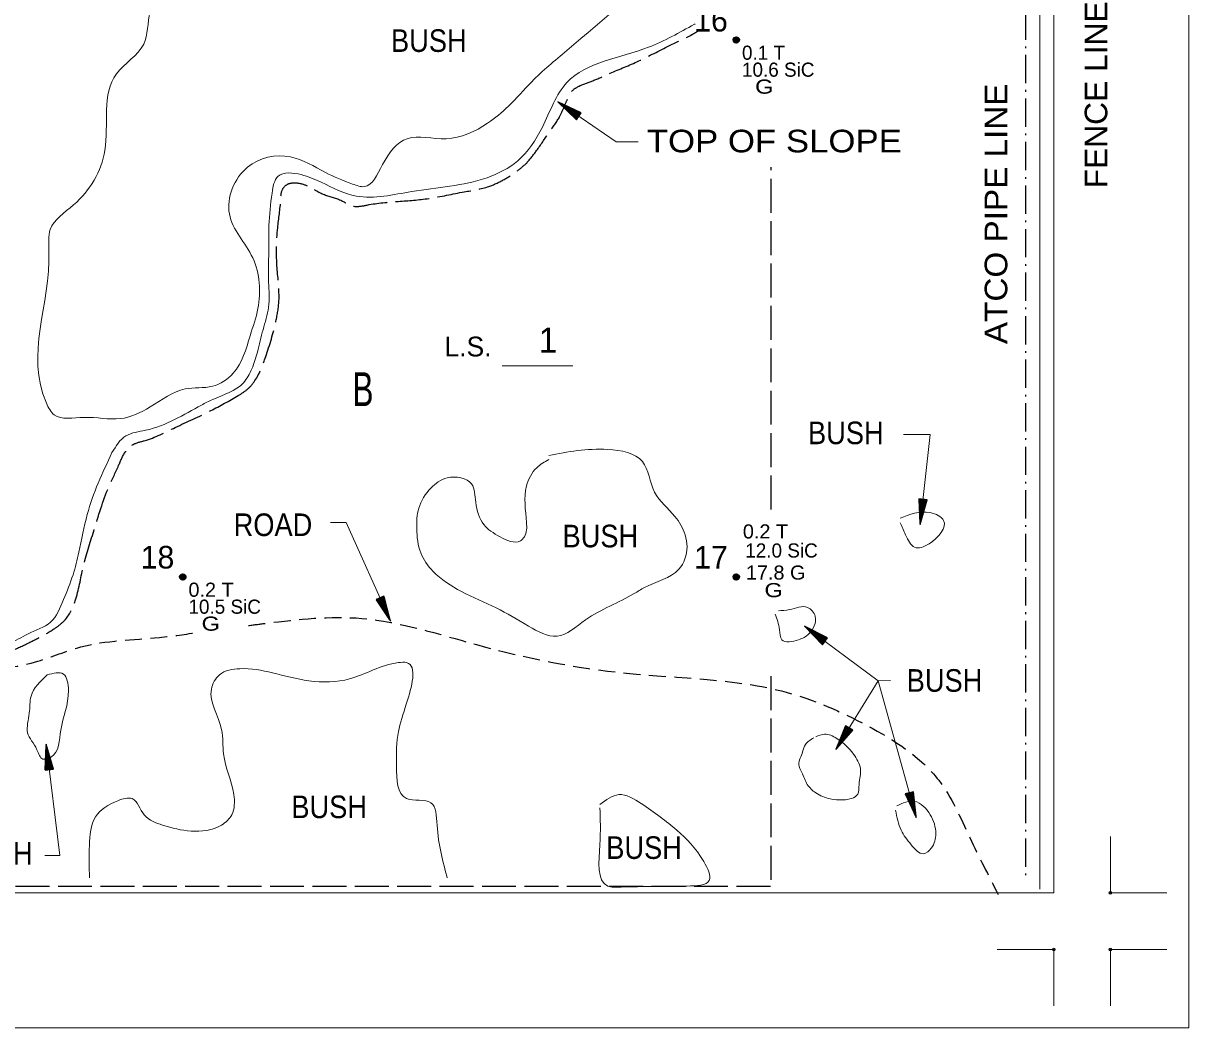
# Model space of a CAD drawing. Extents: x -496 to 480, y -450 to 700.
# Drawn here: x 37.7 to 450, y -450 to -94.7 of the extents above; entities that cross this region are included whole.
import ezdxf
from ezdxf.enums import TextEntityAlignment as Align

# ---------------------------------------------------------------- set-up
doc = ezdxf.new("R2010")
doc.units = 0
doc.header["$LTSCALE"] = 2
doc.header["$PDMODE"] = 32
doc.header["$PDSIZE"] = 1
for name, pattern in [('DOT_DASHED', [7.7, 5, -1.2, 0.3, -1.2]), ('LONG_DASHED', [7.5, 6, -1.5]), ('MEDIUM_DASHED', [4.5, 3, -1.5])]:
    doc.linetypes.add(name, pattern=pattern)
for name, color, linetype, lineweight in [('1', 7, 'Continuous', 13), ('2', 7, 'Continuous', 35), ('3', 7, 'Continuous', 13), ('4', 7, 'Continuous', 25)]:
    doc.layers.add(name, color=color, linetype=linetype, lineweight=lineweight)

msp = doc.modelspace()

# ---------------------------------------------------------------- linework, layer by layer
at = {"layer": '1'}
for p, q in [((207.114, -215.907), (232.114, -215.907)), ((422.281, -402.333), (422.281, -382.333)), ((-402.391, -402.333), (402.281, -402.333)), ((422.281, -402.333), (442.281, -402.333)), ((402.281, -422.333), (382.281, -422.333)), ((402.281, -422.333), (402.281, -442.333)), ((422.281, -422.333), (422.281, -442.333)), ((422.281, -422.333), (442.281, -422.333)), ((-450.017, -450.027), (449.983, -450.027))]:
    msp.add_line(p, q, dxfattribs=at)
for points in [[(449.983, -450.027), (449.983, 399.973), (449.983, 699.973), (-450.017, 699.973), (-450.017, 49.973), (-450.017, -450.027)], [(402.281, -402.333), (402.281, 402.339), (-402.391, 402.339)]]:
    msp.add_lwpolyline(points, dxfattribs=at)
for p in [(422.281, -402.333), (402.281, -422.333), (422.281, -422.333)]:
    msp.add_point(p, dxfattribs=at)
at = {"layer": '2', "linetype": 'LONG_DASHED', "lineweight": 25}
for p, q in [((302.281, -266.667), (302.281, -145.612)), ((302.281, -397.661), (302.281, -324.751)), ((-400, -400), (302.281, -400))]:
    msp.add_line(p, q, dxfattribs=at)
at = {"layer": '2'}
for centre in [(289.948, -100.57), (94.135, -290.569), (289.948, -290.569)]:
    msp.add_circle(centre, 1, dxfattribs=at)
at = {"layer": '2', "linetype": 'LONG_DASHED', "lineweight": 25}
for points in [[(215.795, -144.123), (219.291, -139.726), (223.65, -133.35), (227.23, -128.063), (229.099, -124.02), (230.5, -120.91), (231.745, -118.733), (234.392, -116.867), (239.53, -114.845), (245.29, -112.357), (255.409, -108.003), (266.307, -102.561), (274.247, -98.673), (276.582, -97.273)], [(113.75, -226.394), (117.11, -224.04), (119.657, -221.072), (123.477, -212.593), (127.085, -200.086), (128.146, -192.879), (127.509, -181.22), (127.721, -167.017), (128.782, -157.054), (129.419, -153.45), (131.329, -151.542), (133.451, -151.118), (137.696, -151.966), (143.85, -155.146), (150.005, -157.266), (154.674, -159.386), (159.343, -158.962), (170.379, -157.69), (181.202, -156.63), (193.724, -154.298), (202.425, -152.39), (207.519, -150.059), (212.188, -147.091), (215.795, -144.123)], [(17.819, -315.951), (23.775, -317.83), (30.672, -317.517), (37.256, -315.012), (43.526, -311.88), (48.855, -308.749), (52.304, -305.931), (56.066, -299.042), (58.887, -287.142), (62.649, -274.304), (67.979, -258.647), (71.427, -251.132), (73.935, -246.122), (76.13, -243.93), (80.519, -242.364), (91.491, -237.667), (104.031, -231.717), (113.75, -226.394)]]:
    msp.add_spline(points, degree=3, dxfattribs=at)
at = {"layer": '2'}
for points in [[(289.937, -99.683), (290.668, -100.087), (290.819, -100.936), (290.134, -101.464), (289.325, -101.233), (289.039, -100.475), (289.286, -99.913), (289.859, -99.745), (290.533, -100.239), (290.516, -100.981), (289.999, -101.239), (289.477, -101.07), (289.252, -100.424), (289.836, -99.958), (290.274, -100.492), (290.235, -100.975), (289.606, -100.84), (289.752, -100.205), (290.044, -100.756)], [(94.124, -289.682), (94.855, -290.086), (95.006, -290.935), (94.321, -291.463), (93.512, -291.232), (93.226, -290.474), (93.473, -289.912), (94.046, -289.744), (94.72, -290.238), (94.703, -290.98), (94.186, -291.238), (93.664, -291.069), (93.439, -290.423), (94.023, -289.957), (94.461, -290.491), (94.422, -290.974), (93.793, -290.839), (93.939, -290.204), (94.231, -290.755)], [(289.937, -289.682), (290.668, -290.086), (290.819, -290.935), (290.134, -291.463), (289.325, -291.232), (289.039, -290.474), (289.286, -289.912), (289.859, -289.744), (290.533, -290.238), (290.516, -290.98), (289.999, -291.238), (289.477, -291.069), (289.252, -290.423), (289.836, -289.957), (290.274, -290.491), (290.235, -290.974), (289.606, -290.839), (289.752, -290.204), (290.044, -290.755)]]:
    msp.add_spline(points, degree=3, dxfattribs=at)
at = {"layer": '3', "linetype": 'DOT_DASHED', "lineweight": 25}
msp.add_line((392.281, 402.339), (392.281, -396.11), dxfattribs=at)
at = {"layer": '3'}
msp.add_line((397.281, -401.02), (397.281, 402.339), dxfattribs=at)
for points in [[(269.001, 16.283), (271.297, 22.245), (282.315, 14.908), (294.71, 5.278), (300.22, -8.479), (308.483, -22.236), (318.124, -35.075), (325.929, -51.125), (322.715, -62.589), (318.583, -66.716), (302.515, -66.257), (281.856, -68.092), (271.756, -72.677), (229.979, -104.318), (217.583, -115.323), (209.319, -124.036), (201.974, -129.997), (187.283, -135.5), (173.51, -135.5), (164.787, -144.671), (158.36, -152.467), (154.228, -151.55), (144.587, -147.423), (132.192, -141.92), (117.042, -145.588), (110.615, -162.096), (118.878, -177.688), (120.715, -195.571), (117.96, -205.201), (111.992, -218.499), (104.646, -223.085), (95.006, -224.002), (82.61, -230.422), (72.051, -234.549), (59.196, -234.09), (48.637, -233.173), (45.883, -229.046), (46.801, -175.395), (47.26, -167.599), (55.524, -158.887), (66.542, -139.627), (70.674, -112.572), (80.315, -102.025), (82.61, -90.561), (87.201, -83.683), (93.169, -83.224), (103.728, -88.727), (113.828, -84.6), (122.092, -79.097), (131.733, -74.053), (137.701, -71.302), (145.965, -76.346), (153.31, -77.721), (184.528, -60.755), (205.188, -47.915), (216.206, -36.91), (226.765, -34.158), (236.865, -30.948), (241.456, -24.987), (252.474, -21.777), (259.36, -23.153), (267.165, -28.655), (275.888, -35.534), (280.938, -41.954), (285.988, -44.247), (289.201, -43.329), (291.038, -40.578), (291.956, -37.368), (284.61, -33.241), (279.56, -26.363), (275.888, -20.401), (274.97, -12.147), (272.215, -6.186), (270.379, 3.902), (269.92, 10.322), (269.46, 15.366)], [(275.44, -94.845), (275.13, -95.013), (258.828, -103.155), (230.028, -115.638), (221.334, -131.378), (212.64, -143.319), (201.772, -149.289), (175.146, -154.174), (155.584, -155.803), (143.086, -150.918), (136.022, -148.204), (127.871, -148.747), (125.697, -154.717), (124.611, -166.115)], [(124.611, -166.115), (124.495, -178.364), (124.495, -186.271), (124.495, -195.166), (122.516, -203.073), (120.537, -210.979), (118.558, -216.91), (115.59, -221.851), (104.705, -227.781), (100.747, -229.758), (80.958, -238.653), (74.031, -240.63), (69.084, -246.56)], [(69.084, -246.56), (60.331, -268.438), (57.398, -281.829), (55.303, -289.779), (51.952, -298.567), (47.343, -306.518), (39.383, -310.702), (32.68, -314.05), (26.815, -314.887), (18.669, -313.712)], [(223.64, -247.591), (244.496, -245.436), (256.721, -249.746), (261.036, -260.521), (268.228, -269.141), (271.824, -275.606), (272.543, -279.916), (269.666, -287.817), (257.441, -294.282), (253.845, -296.437), (236.585, -305.775), (226.517, -311.522), (216.449, -307.93), (204.942, -301.465), (192.717, -295.719), (182.649, -288.535), (178.334, -282.071), (176.895, -273.451), (177.614, -266.267), (181.929, -259.084), (187.683, -255.493), (196.312, -257.648), (197.751, -264.112), (200.627, -272.014), (206.381, -276.324), (213.572, -277.761), (215.01, -276.324), (215.73, -271.296), (215.73, -258.366), (219.325, -251.901), (223.64, -249.028)], [(347.883, -269.773), (358.541, -267.802), (363.279, -270.562), (358.147, -278.843), (353.015, -280.025), (349.856, -275.688), (347.883, -271.35)], [(304.852, -302.502), (308.8, -302.107), (315.116, -301.319), (317.88, -304.473), (315.511, -310.782), (311.958, -312.754), (306.036, -312.754), (305.247, -309.205), (303.668, -303.684)], [(61.111, -397.002), (61.111, -385.509), (63.269, -375.452), (71.18, -369.706), (76.214, -368.987), (80.529, -374.734), (87.001, -378.326), (97.069, -380.481), (107.856, -378.326), (111.452, -374.734), (112.171, -367.551), (108.576, -353.184), (107.856, -344.565), (104.261, -330.198), (107.137, -325.17), (114.329, -323.015), (125.835, -324.452), (138.78, -327.325), (153.163, -326.606), (170.423, -320.86), (173.299, -320.86), (173.299, -335.226), (170.423, -345.283), (169.704, -357.494), (173.299, -368.987), (181.929, -370.424), (184.087, -378.326), (187.683, -397.002)], [(46.164, -325.21), (51.883, -324.909), (53.689, -330.622), (50.98, -344.753), (47.368, -354.375), (44.659, -354.976), (42.552, -351.669), (39.241, -345.655), (39.843, -338.74), (40.445, -332.727), (46.164, -325.21)], [(318.042, -347.168), (321.176, -346.179), (325.465, -347.662), (331.404, -353.265), (333.879, -358.373), (333.384, -363.976), (332.889, -367.436), (327.775, -369.414), (323.156, -369.084), (318.042, -366.942), (315.072, -363.976), (313.092, -359.691), (312.103, -356.89), (313.422, -352.441), (314.412, -349.805), (317.382, -347.498)], [(241.688, -371.113), (248.399, -367.564), (256.295, -370.718), (268.928, -380.182), (278.402, -391.223), (280.376, -397.926), (272.481, -399.898), (249.189, -400.292), (244.452, -399.898), (241.688, -385.308), (241.688, -372.296)], [(346.698, -371.507), (353.015, -369.93), (358.541, -374.661), (360.515, -381.365), (358.936, -386.491), (356.173, -388.463), (351.83, -385.308), (348.277, -380.182), (346.303, -373.084)]]:
    msp.add_spline(points, degree=3, dxfattribs=at)
at = {"layer": '3', "linetype": 'MEDIUM_DASHED', "lineweight": 25}
for points in [[(-305.408, -229.098), (-312.128, -232.799), (-334.893, -247.116), (-340.795, -261.433), (-347.54, -283.329), (-355.129, -311.121), (-366.933, -336.386), (-378.737, -368.389), (-379.58, -381.864), (-377.05, -393.654), (-368.619, -397.865), (-361.031, -395.338), (-332.363, -395.338), (-305.383, -384.39), (-260.696, -375.126), (-206.734, -349.861), (-185.655, -347.334), (-140.125, -348.177), (-96.281, -338.071), (-22.084, -321.227), (-2.691, -319.543), (23.446, -322.911), (42.839, -320.385), (58.016, -315.332), (85.84, -311.963), (99.951, -310.092)], [(117.384, -307.75), (123.781, -306.91), (157.508, -305.226), (197.979, -314.49), (251.097, -324.596), (307.589, -331.333), (336.256, -343.124), (361.55, -362.494), (372.511, -382.706), (382.629, -402.918)]]:
    msp.add_spline(points, degree=3, dxfattribs=at)
at = {"layer": '4', "lineweight": 13}
for q in [(325.133, -351.637), (353.558, -375.609)]:
    msp.add_line((340.112, -327.326), q, dxfattribs=at)
for points in [[(255.197, -136.638), (247.467, -136.638), (226.783, -122.447)], [(349.129, -240.14), (358.57, -240.14), (354.96, -272.035)], [(146.375, -271.231), (151.93, -271.231), (167.568, -306.169)], [(344.537, -327.156), (340.112, -327.326), (314.07, -307.945)], [(45.335, -389.154), (50.616, -389.154), (45.801, -349.753)]]:
    msp.add_lwpolyline(points, dxfattribs=at)
at = {"layer": '4'}
for points in [[(226.783, -122.447), (233.356, -128.776), (235.053, -126.302)], [(354.96, -272.035), (357.463, -263.261), (354.482, -262.923)], [(167.568, -306.169), (165.26, -297.341), (162.522, -298.567)], [(314.07, -307.945), (320.394, -314.522), (322.185, -312.115)], [(325.133, -351.637), (331.131, -344.762), (328.577, -343.188)], [(45.801, -349.753), (45.404, -358.869), (48.382, -358.505)], [(353.558, -375.609), (352.588, -366.536), (349.698, -367.341)]]:
    msp.add_lwpolyline(points, close=True, dxfattribs=at)
for points in [[(233.345, -128.661), (227.138, -122.691), (234.883, -126.335), (233.392, -128.535), (227.593, -123.004), (234.69, -126.358), (233.35, -128.369), (228.074, -123.334), (234.477, -126.41), (233.361, -128.181), (228.613, -123.722), (234.247, -126.429), (233.319, -127.954), (229.259, -124.187), (234.016, -126.507), (233.295, -127.702), (229.957, -124.685), (233.705, -126.589), (233.235, -127.446), (230.707, -125.258), (233.382, -126.603), (233.145, -127.148), (231.638, -125.878), (232.986, -126.664)], [(357.367, -263.324), (355.009, -271.607), (354.591, -263.058), (357.233, -263.342), (355.072, -271.058), (354.702, -263.218), (357.107, -263.457), (355.137, -270.478), (354.848, -263.381), (356.935, -263.535), (355.227, -269.821), (354.973, -263.575), (356.755, -263.679), (355.334, -269.032), (355.15, -263.742), (356.543, -263.818), (355.446, -268.181), (355.368, -263.978), (356.345, -263.991), (355.6, -267.251), (355.532, -264.257), (356.125, -264.211), (355.711, -266.138), (355.772, -264.578)], [(165.209, -297.445), (167.392, -305.776), (162.684, -298.628), (165.103, -297.528), (167.167, -305.272), (162.861, -298.709), (165.053, -297.691), (166.928, -304.739), (163.07, -298.775), (164.945, -297.846), (166.671, -304.127), (163.276, -298.879), (164.863, -298.062), (166.362, -303.393), (163.513, -298.933), (164.751, -298.289), (166.026, -302.604), (163.821, -299.025), (164.669, -298.539), (165.686, -301.724), (164.104, -299.182), (164.591, -298.84), (165.214, -300.71), (164.474, -299.336)], [(320.388, -314.407), (314.415, -308.203), (322.014, -312.141), (320.44, -314.282), (314.858, -308.532), (321.82, -312.157), (320.404, -314.115), (315.326, -308.881), (321.606, -312.201), (320.422, -313.928), (315.849, -309.29), (321.375, -312.211), (320.389, -313.699), (316.477, -309.779), (321.142, -312.28), (320.376, -313.446), (317.156, -310.303), (320.828, -312.35), (320.325, -313.188), (317.882, -310.905), (320.504, -312.351), (320.246, -312.887), (318.789, -311.56), (320.106, -312.397)], [(331.017, -344.778), (325.36, -351.271), (328.618, -343.357), (330.889, -344.737), (325.649, -350.801), (328.651, -343.548), (330.726, -344.788), (325.956, -350.304), (328.713, -343.758), (330.537, -344.786), (326.317, -349.747), (328.744, -343.987), (330.312, -344.839), (326.749, -349.079), (328.833, -344.214), (330.062, -344.875), (327.213, -348.357), (328.93, -344.52), (329.809, -344.947), (327.748, -347.581), (328.96, -344.842), (329.516, -345.052), (328.321, -346.62), (329.04, -345.235)], [(45.483, -358.785), (45.853, -350.18), (48.245, -358.399), (45.608, -358.736), (45.92, -350.729), (48.1, -358.269), (45.705, -358.595), (45.991, -351.308), (47.92, -358.144), (45.853, -358.479), (46.056, -351.969), (47.753, -357.984), (45.996, -358.297), (46.135, -352.761), (47.542, -357.863), (46.169, -358.113), (46.223, -353.614), (47.275, -357.684), (46.322, -357.899), (46.289, -354.555), (47.051, -357.451), (46.485, -357.634), (46.44, -355.663), (46.743, -357.194)], [(352.522, -366.631), (353.443, -375.194), (349.85, -367.426), (352.406, -366.698), (353.295, -374.662), (350.012, -367.532), (352.332, -366.851), (353.138, -374.099), (350.209, -367.628), (352.202, -366.989), (352.975, -373.456), (350.398, -367.762), (352.088, -367.19), (352.779, -372.685), (350.624, -367.85), (351.944, -367.398), (352.563, -371.854), (350.915, -367.987), (351.826, -367.633), (352.358, -370.934), (351.172, -368.184), (351.704, -367.919), (352.042, -369.86), (351.514, -368.392)]]:
    msp.add_lwpolyline(points, dxfattribs=at)

# ---------------------------------------------------------------- texts
at = {"layer": '1'}
for s, height, p in [('L.S.', 7, (195.033, -212.53)), ('1', 8.89, (223.338, -211.189))]:
    msp.add_text(s, height=height, dxfattribs=at).set_placement(p, align=Align.CENTER)
at = {"layer": '2'}
for s, p in [(' 16', (286.948, -97.57)), (' 18', (91.135, -287.569)), (' 17', (286.948, -287.569))]:
    msp.add_text(s, height=8, dxfattribs=at).set_placement(p, align=Align.RIGHT)
for s, p in [('0.1 T      ', (291.948, -107.57)), ('10.6 SiC   ', (291.948, -113.57)), ('12.0 SiC   ', (293.119, -283.69)), ('10.5 SiC   ', (96.135, -303.569))]:
    msp.add_text(s, height=5, dxfattribs=at).set_placement(p)
for s, width, p in [('  G        ', 1.25, (291.948, -119.57)), ('0.2 T      ', 1.05, (292.267, -276.945)), ('17.8 G     ', 1.05, (293.332, -291.497)), ('0.2 T      ', 1.05, (96.135, -297.569)), ('  G        ', 1.25, (295.247, -297.71)), ('  G        ', 1.25, (96.135, -309.569))]:
    msp.add_text(s, height=5, dxfattribs=dict(at, width=width)).set_placement(p)
at = {"layer": '2', "width": 0.7}
msp.add_text('B', height=12, dxfattribs=at).set_placement((157.851, -230.12), align=Align.CENTER)
at = {"layer": '4'}
for s, width, p in [('FENCE LINE', 1.05, (421.196, -119.997)), ('ATCO PIPE LINE', 1.1, (385.809, -162.076))]:
    msp.add_text(s, height=8, rotation=90, dxfattribs=dict(at, width=width)).set_placement(p, align=Align.CENTER)
for s, width, p in [('BUSH', 0.9, (181.171, -104.793)), ('TOP OF SLOPE', 1.15, (303.392, -140.326)), ('BUSH', 0.9, (328.695, -243.58)), ('ROAD', 0.9, (126.036, -276.084)), ('BUSH', 0.9, (241.848, -280.079)), ('BUSH', 0.9, (363.604, -331.177)), ('BUSH', 0.9, (145.923, -375.892)), ('BUSH', 0.9, (257.319, -390.315)), ('BUSH', 0.9, (27.629, -392.383))]:
    msp.add_text(s, height=8, dxfattribs=dict(at, width=width)).set_placement(p, align=Align.CENTER)

doc.saveas('drawing.dxf')
